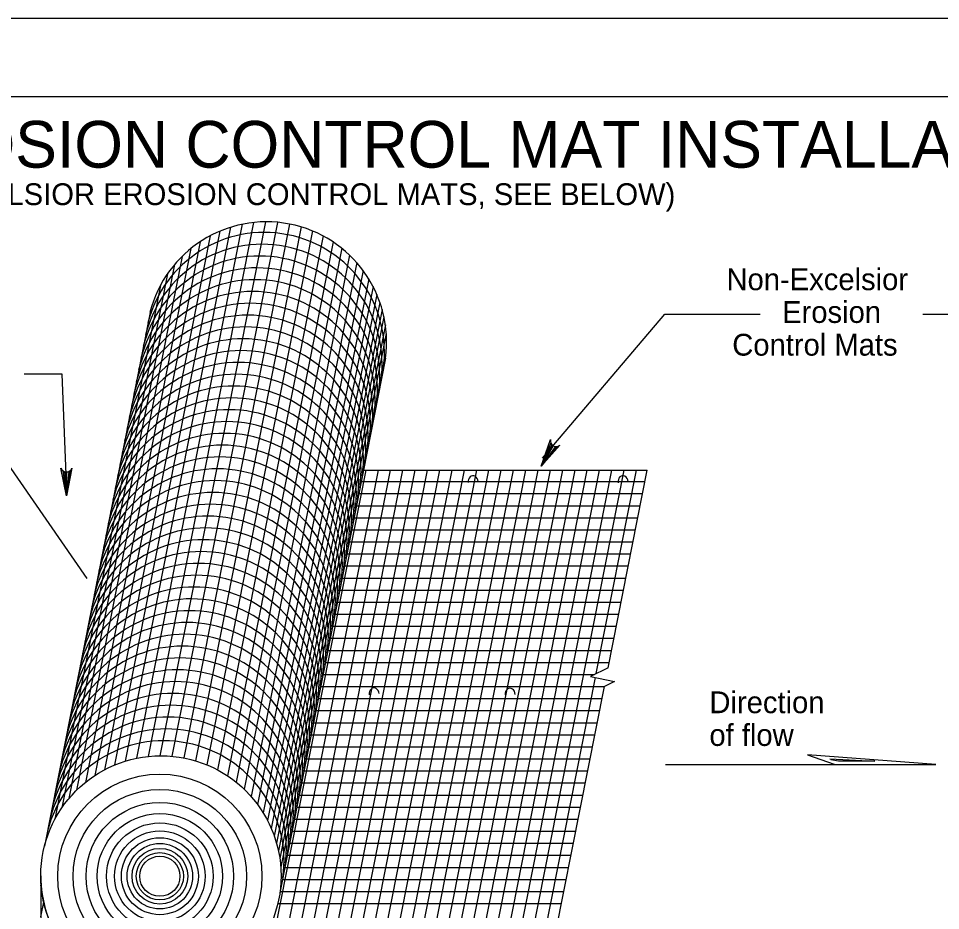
# Model space of a CAD drawing. Extents: x 1083.1 to 1117.1, y 719.4 to 741.4.
# Drawn here: x 1098.57 to 1104.49, y 735.63 to 741.35 of the extents above; entities that cross this region are included whole.
import ezdxf

# ---------------------------------------------------------------- set-up
doc = ezdxf.new("R2010")
doc.units = 0
for name, color, linetype in [('SH_Border', 7, 'Continuous'), ('SH_Cut_Line', 7, 'Continuous'), ('ST_Details', 7, 'Continuous'), ('ST_Text', 7, 'Continuous')]:
    doc.layers.add(name, color=color, linetype=linetype)

msp = doc.modelspace()

# ---------------------------------------------------------------- linework, layer by layer
at = {"layer": 'SH_Border'}
msp.add_lwpolyline([(1085.1264, 740.8541), (1116.6264, 740.8541), (1116.6264, 719.8541), (1085.1264, 719.8541)], close=True, dxfattribs=at)
at = {"layer": 'SH_Cut_Line'}
msp.add_lwpolyline([(1083.1264, 719.3541), (1117.1264, 719.3541), (1117.1264, 741.3541), (1083.1264, 741.3541)], close=True, dxfattribs=at)
at = {"layer": 'ST_Details'}
for p, q in [((1099.2579, 736.5876), (1099.9353, 740.0144)), ((1099.3316, 736.6064), (1100.0091, 740.0333)), ((1099.4054, 736.6179), (1100.0826, 740.0447)), ((1100.1561, 740.0489), (1099.4787, 736.622)), ((1099.5588, 736.6186), (1100.2361, 740.0454)), ((1100.3102, 740.0347), (1099.6329, 736.6079)), ((1100.3852, 740.0162), (1099.7079, 736.5894)), ((1099.8009, 739.9584), (1099.1236, 736.5316)), ((1099.1897, 736.5629), (1099.8671, 739.9898)), ((1100.4582, 739.9901), (1099.7809, 736.5634)), ((1100.5266, 739.9578), (1099.8491, 736.5311)), ((1099.6786, 739.8776), (1099.0013, 736.4507)), ((1099.7382, 739.9212), (1099.0609, 736.4944)), ((1100.5902, 739.9196), (1099.9129, 736.4929)), ((1100.6458, 739.879), (1099.9686, 736.4523)), ((1099.6219, 739.8269), (1098.9446, 736.4001)), ((1100.6965, 739.8346), (1100.0191, 736.4079)), ((1099.5732, 739.7742), (1098.8959, 736.3474)), ((1100.7421, 739.7869), (1100.0648, 736.3602)), ((1099.5272, 739.7139), (1098.8499, 736.2869)), ((1100.783, 739.7363), (1100.1056, 736.3095)), ((1099.4831, 739.6411), (1098.8057, 736.2142)), ((1100.8191, 739.6829), (1100.1418, 736.2563)), ((1100.8474, 739.6329), (1100.1701, 736.2064)), ((1100.8714, 739.5825), (1100.1941, 736.1559)), ((1100.8911, 739.5319), (1100.2136, 736.1053)), ((1099.4158, 739.4671), (1098.7386, 736.0408)), ((1100.9054, 739.4864), (1100.228, 736.0599)), ((1100.9171, 739.4388), (1100.2397, 736.0121)), ((1104.3756, 739.4562), (1104.9669, 739.4562)), ((1100.9261, 739.3882), (1100.2488, 735.9617)), ((1100.9321, 739.3327), (1100.2548, 735.9062)), ((1100.9271, 739.1733), (1100.7852, 738.4558)), ((1101.9877, 738.6296), (1101.9251, 738.4804)), ((1101.9945, 738.6193), (1101.9251, 738.4804)), ((1102.0034, 738.6121), (1101.9251, 738.4804)), ((1102.0172, 738.6072), (1101.9251, 738.4804)), ((1102.0292, 738.6071), (1101.9251, 738.4804)), ((1099.0136, 737.7593), (1098.5056, 738.4926)), ((1100.1352, 735.0804), (1100.8024, 738.4558)), ((1100.2141, 735.0804), (1100.8813, 738.4558)), ((1100.7852, 738.4558), (1100.2489, 735.7423)), ((1100.293, 735.0804), (1100.9601, 738.4558)), ((1100.3719, 735.0804), (1101.0391, 738.4558)), ((1100.4507, 735.0804), (1101.1179, 738.4558)), ((1100.5296, 735.0804), (1101.1968, 738.4558)), ((1100.6085, 735.0804), (1101.2756, 738.4558)), ((1100.6874, 735.0804), (1101.3546, 738.4558)), ((1100.7662, 735.0804), (1101.4335, 738.4558)), ((1100.7852, 738.4558), (1102.6066, 738.4558)), ((1100.8451, 735.0804), (1101.5123, 738.4558)), ((1100.924, 735.0804), (1101.5911, 738.4558)), ((1101.0029, 735.0804), (1101.67, 738.4558)), ((1101.0818, 735.0804), (1101.7489, 738.4558)), ((1101.1606, 735.0804), (1101.8277, 738.4558)), ((1101.2396, 735.0804), (1101.9066, 738.4558)), ((1101.3184, 735.0804), (1101.9855, 738.4558)), ((1101.3973, 735.0804), (1102.0644, 738.4558)), ((1101.4761, 735.0804), (1102.1433, 738.4558)), ((1101.5551, 735.0804), (1102.2221, 738.4558)), ((1101.6339, 735.0804), (1102.3011, 738.4558)), ((1101.7128, 735.0804), (1102.3799, 738.4558)), ((1101.7917, 735.0804), (1102.4588, 738.4558)), ((1102.2795, 737.1494), (1102.5376, 738.4558)), ((1102.3557, 737.1864), (1102.6066, 738.4558)), ((1098.8571, 738.4504), (1098.8795, 738.2902)), ((1098.8681, 738.4449), (1098.8795, 738.2902)), ((1098.9042, 738.4523), (1098.8795, 738.2902)), ((1098.8939, 738.4461), (1098.8795, 738.2902)), ((1098.8795, 738.4434), (1098.8795, 738.2902)), ((1100.7706, 738.3815), (1102.592, 738.3815)), ((1100.7553, 738.3042), (1102.5766, 738.3042)), ((1100.7401, 738.2268), (1102.5614, 738.2268)), ((1100.7248, 738.1494), (1102.5461, 738.1494)), ((1100.7095, 738.072), (1102.5307, 738.072)), ((1100.6942, 737.9947), (1102.5155, 737.9947)), ((1100.6789, 737.9173), (1102.5002, 737.9173)), ((1100.6636, 737.8399), (1102.4849, 737.8399)), ((1100.6483, 737.7625), (1102.4696, 737.7625)), ((1100.633, 737.6852), (1102.4543, 737.6852)), ((1100.6177, 737.6078), (1102.4391, 737.6078)), ((1100.6024, 737.5304), (1102.4237, 737.5304)), ((1100.5871, 737.4531), (1102.4084, 737.4531)), ((1100.5718, 737.3757), (1102.3931, 737.3757)), ((1100.5566, 737.2984), (1102.3778, 737.2984)), ((1100.5413, 737.2209), (1102.3625, 737.2209)), ((1102.3556, 737.1863), (1102.2419, 737.1313)), ((1100.526, 737.1436), (1102.2674, 737.1436)), ((1101.8705, 735.0804), (1102.2745, 737.1242)), ((1102.2419, 737.1313), (1102.3965, 737.0975)), ((1102.3965, 737.0975), (1102.3319, 737.0662)), ((1100.5107, 737.0662), (1102.3319, 737.0662)), ((1101.9395, 735.0804), (1102.332, 737.0662)), ((1100.4954, 736.9889), (1102.3167, 736.9889)), ((1100.4801, 736.9114), (1102.3014, 736.9114)), ((1100.4648, 736.8341), (1102.2861, 736.8341)), ((1100.4495, 736.7567), (1102.2708, 736.7567)), ((1100.4342, 736.6794), (1102.2555, 736.6794)), ((1104.459, 736.5654), (1103.6356, 736.628)), ((1103.6356, 736.628), (1103.8069, 736.5679)), ((1100.4189, 736.6019), (1102.2401, 736.6019)), ((1102.7229, 736.5654), (1104.459, 736.5654)), ((1103.7795, 736.6019), (1104.0671, 736.5862)), ((1103.834, 736.5862), (1103.7845, 736.5966)), ((1104.0671, 736.5862), (1103.834, 736.5862)), ((1100.4036, 736.5246), (1102.2249, 736.5246)), ((1100.3883, 736.4472), (1102.2096, 736.4472)), ((1100.3731, 736.3699), (1102.1942, 736.3699)), ((1100.3578, 736.2925), (1102.179, 736.2925)), ((1100.3425, 736.2151), (1102.1636, 736.2151)), ((1100.3271, 736.1378), (1102.1483, 736.1378)), ((1100.3119, 736.0604), (1102.1331, 736.0604)), ((1100.2966, 735.983), (1102.1178, 735.983)), ((1098.7149, 735.8513), (1098.7149, 734.0895)), ((1100.2813, 735.9056), (1102.1026, 735.9056)), ((1098.7149, 735.788), (1098.7168, 735.7976)), ((1100.266, 735.8283), (1102.0872, 735.8283)), ((1100.2506, 735.7509), (1102.0719, 735.7509)), ((1098.7149, 735.5886), (1098.7336, 735.683)), ((1100.2359, 735.6735), (1102.0566, 735.6735)), ((1100.2071, 735.6653), (1100.2071, 735.6653))]:
    msp.add_line(p, q, dxfattribs=at)
for points in [[(1101.9342, 738.5328), (1102.7192, 739.4562), (1103.3308, 739.4562)], [(1098.8823, 738.3208), (1098.853, 739.0716), (1098.6089, 739.0716)], [(1102.046, 738.6145), (1101.9251, 738.4804), (1101.9851, 738.6506)], [(1098.9149, 738.4672), (1098.8795, 738.2902), (1098.8441, 738.4672)]]:
    msp.add_lwpolyline(points, dxfattribs=at)
for centre, start, end in [((1102.0228, 738.6449), 171.38675, 307.21287), ((1098.8794, 738.4815), 202.08782, 337.91395)]:
    msp.add_arc(centre, 0.0382, start, end, dxfattribs=at)
for centre, major_axis, ratio, start_param, end_param in [((1100.1631, 739.278), (0.7709, 0), 0.999895, 6.146961, 9.176969), ((1100.1495, 739.21), (-0.7709, 0), 0.999895, 2.999709, 6.034797), ((1100.1346, 739.1341), (-0.7709, 0), 0.999895, 2.999709, 6.034797), ((1100.1196, 739.0582), (-0.7709, 0), 0.999895, 2.999709, 6.034797), ((1100.1046, 738.9823), (-0.7709, 0), 0.999895, 2.999709, 6.034797), ((1100.0896, 738.9065), (-0.7709, 0), 0.999895, 2.999709, 6.034797), ((1100.0746, 738.8306), (-0.7709, 0), 0.999895, 2.999709, 6.034797), ((1100.0596, 738.7547), (-0.7709, 0), 0.999895, 2.999709, 6.034797), ((1100.0446, 738.6788), (-0.7709, 0), 0.999895, 2.999709, 6.034797), ((1100.0296, 738.603), (-0.7709, 0), 0.999895, 2.999709, 6.034797), ((1100.0146, 738.5271), (-0.7709, 0), 0.999895, 2.999709, 6.034797), ((1099.9995, 738.4512), (-0.7709, 0), 0.999895, 2.999709, 6.034797), ((1099.9845, 738.3754), (-0.7709, 0), 0.999895, 2.999709, 6.034797), ((1099.9695, 738.2995), (-0.7709, 0), 0.999895, 2.999709, 6.034797), ((1099.9546, 738.2236), (-0.7709, 0), 0.999895, 2.999709, 6.034797), ((1099.9396, 738.1477), (-0.7709, 0), 0.999895, 2.999709, 6.034797), ((1099.9246, 738.0719), (-0.7709, 0), 0.999895, 2.999709, 6.034797), ((1099.9096, 737.996), (-0.7709, 0), 0.999895, 2.999709, 6.034797), ((1099.8946, 737.9201), (-0.7709, 0), 0.999895, 2.999709, 6.034797), ((1099.8796, 737.8442), (-0.7709, 0), 0.999895, 2.999709, 6.034797), ((1099.8646, 737.7684), (-0.7709, 0), 0.999895, 2.999709, 6.034797), ((1099.8496, 737.6925), (-0.7709, 0), 0.999895, 2.999709, 6.034797), ((1099.8346, 737.6166), (-0.7709, 0), 0.999895, 2.999709, 6.034797), ((1101.4902, 738.3785), (-0.0049, 0.0407), 0.788117, 4.712337, 7.85393), ((1102.4516, 738.3782), (-0.0049, 0.0407), 0.788117, 4.712337, 7.85393), ((1099.8196, 737.5408), (-0.7709, 0), 0.999895, 2.999709, 6.034797), ((1099.8046, 737.4649), (-0.7709, 0), 0.999895, 2.999709, 6.034797), ((1099.7896, 737.389), (-0.7709, 0), 0.999895, 2.999709, 6.034797), ((1099.7746, 737.3131), (-0.7709, 0), 0.999895, 2.999709, 6.034797), ((1099.7596, 737.2373), (-0.7709, 0), 0.999895, 2.999709, 6.034797), ((1099.7447, 737.1614), (-0.7709, 0), 0.999895, 2.999709, 6.034797), ((1099.7297, 737.0855), (-0.7709, 0), 0.999895, 2.999709, 6.034797), ((1099.7147, 737.0096), (-0.7709, 0), 0.999895, 2.999709, 6.034797), ((1099.6997, 736.9338), (-0.7709, 0), 0.999895, 2.999709, 6.034797), ((1099.6847, 736.8579), (-0.7709, 0), 0.999895, 2.999709, 6.034797), ((1099.6697, 736.782), (-0.7709, 0), 0.999895, 2.999709, 6.034797), ((1099.6547, 736.7061), (-0.7709, 0), 0.999895, 2.999709, 6.034797), ((1099.6397, 736.6303), (-0.7709, 0), 0.999895, 2.999709, 6.034797), ((1099.6247, 736.5544), (-0.7709, 0), 0.999895, 2.999709, 6.034797), ((1099.6097, 736.4785), (-0.7709, 0), 0.999895, 2.999709, 6.034797), ((1099.5947, 736.4027), (-0.7709, 0), 0.999895, 2.999709, 6.034797), ((1099.5797, 736.3268), (-0.7709, 0), 0.999895, 2.999709, 6.034797), ((1099.5647, 736.2509), (-0.7709, 0), 0.999895, 2.999709, 6.034797), ((1100.8546, 737.0167), (-0.0049, 0.0407), 0.788117, 4.712337, 7.85393), ((1101.7268, 737.0142), (-0.0017, 0.0409), 0.788119, 4.71237, 7.853963), ((1099.5497, 736.175), (-0.7709, 0), 0.999895, 2.999709, 6.034797), ((1099.5348, 736.0992), (-0.7709, 0), 0.999895, 2.999709, 6.034797), ((1099.5198, 736.0233), (-0.7709, 0), 0.999895, 2.999709, 6.034797), ((1099.5048, 735.9474), (-0.7709, 0), 0.999895, 2.999709, 6.034797), ((1099.4866, 735.8516), (-0.7717, 0), 0.999895, 0.000493, 0.627514)]:
    msp.add_ellipse(centre, major_axis=major_axis, ratio=ratio, start_param=start_param, end_param=end_param, dxfattribs=at)
for centre, major_axis in [((1099.4859, 735.8512), (0.7709, 0)), ((1099.479, 735.8487), (0.6553, 0)), ((1099.479, 735.8487), (0.557, 0)), ((1099.479, 735.8487), (0.4734, 0)), ((1099.479, 735.8487), (0.4024, 0)), ((1099.479, 735.8487), (0.3421, 0)), ((1099.479, 735.8487), (0.2907, 0)), ((1099.479, 735.8487), (0.2471, 0)), ((1099.479, 735.8487), (0.2101, 0)), ((1099.479, 735.8487), (0.1786, 0)), ((1099.479, 735.8487), (0.1518, 0)), ((1099.479, 735.8487), (0.129, 0))]:
    msp.add_ellipse(centre, major_axis=major_axis, ratio=0.999895, dxfattribs=at)

# ---------------------------------------------------------------- texts
at = {"layer": 'ST_Text'}
for s, height, p in [('NON-EXCELSIOR EROSION CONTROL MAT INSTALLATION', 0.3, (1094.2488, 740.3963)), ('(FOR EXCELSIOR EROSION CONTROL MATS, SEE BELOW)', 0.14, (1097.4819, 740.156)), ('Non-Excelsior', 0.14, (1103.1153, 739.6099)), ('Erosion', 0.14, (1103.4723, 739.3999)), ('Control Mats', 0.14, (1103.1522, 739.1899)), ('Direction', 0.14, (1103.0056, 736.895)), ('of flow', 0.14, (1103.0056, 736.685))]:
    msp.add_text(s, height=height, dxfattribs=at).set_placement(p)

doc.saveas('drawing.dxf')
